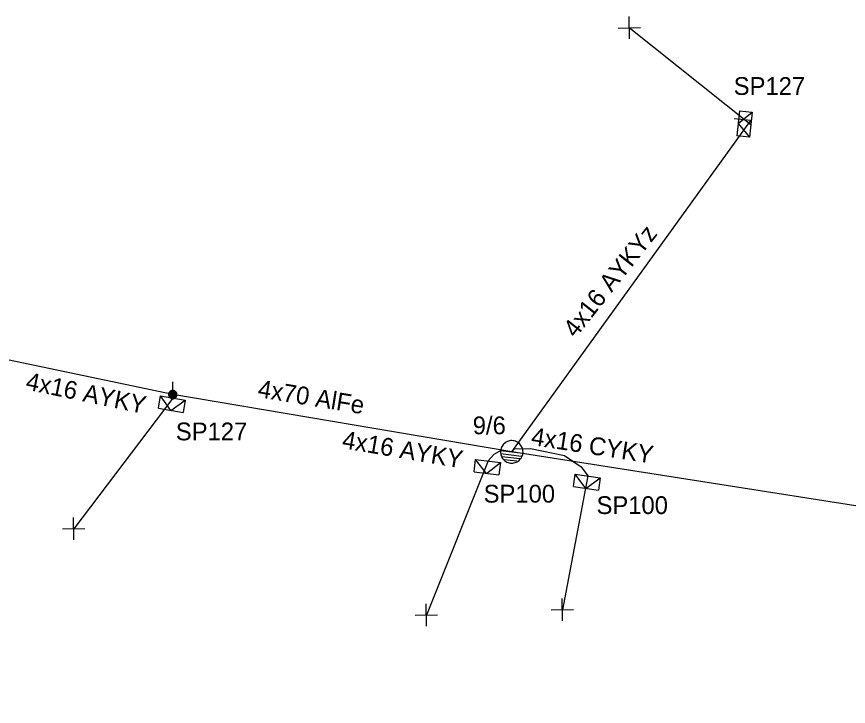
# Model space of a CAD drawing. Extents: x -762504 to -761250, y -1152974 to -1152253.
# Drawn here: x -761447.44 to -761400.94, y -1152551.93 to -1152513.38 of the extents above; entities that cross this region are included whole.
import ezdxf

# ---------------------------------------------------------------- set-up
doc = ezdxf.new("R2010")
doc.units = 0
for name, color, linetype in [('Vrstva 1', 7, 'Continuous'), ('Vrstva 12', 7, 'Continuous'), ('Vrstva 13', 7, 'Continuous'), ('Vrstva 2', 7, 'Continuous'), ('Vrstva 31', 7, 'Continuous'), ('Vrstva 33', 7, 'Continuous'), ('Vrstva 34', 7, 'Continuous'), ('Vrstva 52', 7, 'Continuous'), ('Vrstva 54', 7, 'Continuous'), ('Vrstva 55', 7, 'Continuous'), ('Vrstva 59', 7, 'Continuous')]:
    doc.layers.add(name, color=color, linetype=linetype)

msp = doc.modelspace()

# ---------------------------------------------------------------- linework, layer by layer
at = {"layer": 'Vrstva 1'}
msp.add_lwpolyline([(-761359.26, -1152551.93), (-761388.43, -1152542.63), (-761419.76, -1152537.7), (-761438.71, -1152534.5), (-761457.83, -1152530.5)], dxfattribs=at)
at = {"layer": 'Vrstva 13'}
for points in [[(-761406.392, -1152519.189), (-761407.324, -1152519.091)], [(-761438.71, -1152534.266), (-761438.71, -1152533.796)], [(-761438.475, -1152534.501), (-761438.476, -1152534.477), (-761438.48, -1152534.452), (-761438.486, -1152534.429), (-761438.495, -1152534.406), (-761438.506, -1152534.384), (-761438.519, -1152534.363), (-761438.535, -1152534.344), (-761438.552, -1152534.327), (-761438.571, -1152534.311), (-761438.592, -1152534.298), (-761438.614, -1152534.287), (-761438.637, -1152534.278), (-761438.661, -1152534.271), (-761438.685, -1152534.267), (-761438.71, -1152534.266), (-761438.734, -1152534.267), (-761438.758, -1152534.271), (-761438.782, -1152534.278), (-761438.805, -1152534.287), (-761438.827, -1152534.298), (-761438.848, -1152534.311), (-761438.867, -1152534.327), (-761438.884, -1152534.344), (-761438.9, -1152534.363), (-761438.913, -1152534.384), (-761438.924, -1152534.406), (-761438.933, -1152534.429), (-761438.939, -1152534.452), (-761438.943, -1152534.477), (-761438.945, -1152534.501), (-761438.943, -1152534.526), (-761438.939, -1152534.55), (-761438.933, -1152534.574), (-761438.924, -1152534.597), (-761438.913, -1152534.619), (-761438.9, -1152534.639), (-761438.884, -1152534.658), (-761438.867, -1152534.676), (-761438.848, -1152534.691), (-761438.827, -1152534.705), (-761438.805, -1152534.716), (-761438.782, -1152534.725), (-761438.758, -1152534.731), (-761438.734, -1152534.735), (-761438.71, -1152534.736), (-761438.685, -1152534.735), (-761438.661, -1152534.731), (-761438.637, -1152534.725), (-761438.614, -1152534.716), (-761438.592, -1152534.705), (-761438.571, -1152534.691), (-761438.552, -1152534.676), (-761438.535, -1152534.658), (-761438.519, -1152534.639), (-761438.506, -1152534.619), (-761438.495, -1152534.597), (-761438.486, -1152534.574), (-761438.48, -1152534.55), (-761438.476, -1152534.526), (-761438.475, -1152534.501)], [(-761438.475, -1152534.501), (-761438.476, -1152534.477), (-761438.48, -1152534.452), (-761438.486, -1152534.429), (-761438.495, -1152534.406), (-761438.506, -1152534.384), (-761438.519, -1152534.363), (-761438.535, -1152534.344), (-761438.552, -1152534.327), (-761438.571, -1152534.311), (-761438.592, -1152534.298), (-761438.614, -1152534.287), (-761438.637, -1152534.278), (-761438.661, -1152534.271), (-761438.685, -1152534.267), (-761438.71, -1152534.266), (-761438.734, -1152534.267), (-761438.758, -1152534.271), (-761438.782, -1152534.278), (-761438.805, -1152534.287), (-761438.827, -1152534.298), (-761438.848, -1152534.311), (-761438.867, -1152534.327), (-761438.884, -1152534.344), (-761438.9, -1152534.363), (-761438.913, -1152534.384), (-761438.924, -1152534.406), (-761438.933, -1152534.429), (-761438.939, -1152534.452), (-761438.943, -1152534.477), (-761438.945, -1152534.501), (-761438.943, -1152534.526), (-761438.939, -1152534.55), (-761438.933, -1152534.574), (-761438.924, -1152534.597), (-761438.913, -1152534.619), (-761438.9, -1152534.639), (-761438.884, -1152534.658), (-761438.867, -1152534.676), (-761438.848, -1152534.691), (-761438.827, -1152534.705), (-761438.805, -1152534.716), (-761438.782, -1152534.725), (-761438.758, -1152534.731), (-761438.734, -1152534.735), (-761438.71, -1152534.736), (-761438.685, -1152534.735), (-761438.661, -1152534.731), (-761438.637, -1152534.725), (-761438.614, -1152534.716), (-761438.592, -1152534.705), (-761438.571, -1152534.691), (-761438.552, -1152534.676), (-761438.535, -1152534.658), (-761438.519, -1152534.639), (-761438.506, -1152534.619), (-761438.495, -1152534.597), (-761438.486, -1152534.574), (-761438.48, -1152534.55), (-761438.476, -1152534.526), (-761438.475, -1152534.501)], [(-761438.504, -1152534.501), (-761438.505, -1152534.48), (-761438.509, -1152534.458), (-761438.514, -1152534.438), (-761438.522, -1152534.418), (-761438.532, -1152534.399), (-761438.543, -1152534.38), (-761438.557, -1152534.364), (-761438.572, -1152534.349), (-761438.589, -1152534.335), (-761438.607, -1152534.323), (-761438.626, -1152534.314), (-761438.646, -1152534.306), (-761438.667, -1152534.3), (-761438.688, -1152534.297), (-761438.71, -1152534.296), (-761438.731, -1152534.297), (-761438.752, -1152534.3), (-761438.773, -1152534.306), (-761438.793, -1152534.314), (-761438.812, -1152534.323), (-761438.83, -1152534.335), (-761438.847, -1152534.349), (-761438.862, -1152534.364), (-761438.876, -1152534.38), (-761438.887, -1152534.399), (-761438.897, -1152534.418), (-761438.905, -1152534.438), (-761438.91, -1152534.458), (-761438.914, -1152534.48), (-761438.915, -1152534.501), (-761438.914, -1152534.523), (-761438.91, -1152534.544), (-761438.905, -1152534.565), (-761438.897, -1152534.585), (-761438.887, -1152534.604), (-761438.876, -1152534.622), (-761438.862, -1152534.639), (-761438.847, -1152534.654), (-761438.83, -1152534.667), (-761438.812, -1152534.679), (-761438.793, -1152534.689), (-761438.773, -1152534.697), (-761438.752, -1152534.702), (-761438.731, -1152534.705), (-761438.71, -1152534.707), (-761438.688, -1152534.705), (-761438.667, -1152534.702), (-761438.646, -1152534.697), (-761438.626, -1152534.689), (-761438.607, -1152534.679), (-761438.589, -1152534.667), (-761438.572, -1152534.654), (-761438.557, -1152534.639), (-761438.543, -1152534.622), (-761438.532, -1152534.604), (-761438.522, -1152534.585), (-761438.514, -1152534.565), (-761438.509, -1152534.544), (-761438.505, -1152534.523), (-761438.504, -1152534.501)], [(-761438.534, -1152534.501), (-761438.535, -1152534.483), (-761438.538, -1152534.465), (-761438.542, -1152534.447), (-761438.549, -1152534.43), (-761438.557, -1152534.413), (-761438.567, -1152534.398), (-761438.579, -1152534.384), (-761438.592, -1152534.371), (-761438.606, -1152534.359), (-761438.622, -1152534.349), (-761438.638, -1152534.341), (-761438.655, -1152534.334), (-761438.673, -1152534.329), (-761438.691, -1152534.326), (-761438.71, -1152534.325), (-761438.728, -1152534.326), (-761438.746, -1152534.329), (-761438.764, -1152534.334), (-761438.781, -1152534.341), (-761438.797, -1152534.349), (-761438.813, -1152534.359), (-761438.827, -1152534.371), (-761438.84, -1152534.384), (-761438.852, -1152534.398), (-761438.862, -1152534.413), (-761438.87, -1152534.43), (-761438.877, -1152534.447), (-761438.881, -1152534.465), (-761438.884, -1152534.483), (-761438.885, -1152534.501), (-761438.884, -1152534.52), (-761438.881, -1152534.538), (-761438.877, -1152534.555), (-761438.87, -1152534.573), (-761438.862, -1152534.589), (-761438.852, -1152534.604), (-761438.84, -1152534.619), (-761438.827, -1152534.632), (-761438.813, -1152534.643), (-761438.797, -1152534.653), (-761438.781, -1152534.662), (-761438.764, -1152534.668), (-761438.746, -1152534.673), (-761438.728, -1152534.676), (-761438.71, -1152534.677), (-761438.691, -1152534.676), (-761438.673, -1152534.673), (-761438.655, -1152534.668), (-761438.638, -1152534.662), (-761438.622, -1152534.653), (-761438.606, -1152534.643), (-761438.592, -1152534.632), (-761438.579, -1152534.619), (-761438.567, -1152534.604), (-761438.557, -1152534.589), (-761438.549, -1152534.573), (-761438.542, -1152534.555), (-761438.538, -1152534.538), (-761438.535, -1152534.52), (-761438.534, -1152534.501)], [(-761438.563, -1152534.501), (-761438.564, -1152534.486), (-761438.567, -1152534.471), (-761438.571, -1152534.456), (-761438.576, -1152534.442), (-761438.583, -1152534.428), (-761438.591, -1152534.415), (-761438.601, -1152534.403), (-761438.612, -1152534.393), (-761438.624, -1152534.383), (-761438.637, -1152534.375), (-761438.65, -1152534.368), (-761438.664, -1152534.362), (-761438.679, -1152534.358), (-761438.694, -1152534.356), (-761438.71, -1152534.355), (-761438.725, -1152534.356), (-761438.74, -1152534.358), (-761438.755, -1152534.362), (-761438.769, -1152534.368), (-761438.783, -1152534.375), (-761438.795, -1152534.383), (-761438.807, -1152534.393), (-761438.818, -1152534.403), (-761438.828, -1152534.415), (-761438.836, -1152534.428), (-761438.843, -1152534.442), (-761438.849, -1152534.456), (-761438.853, -1152534.471), (-761438.855, -1152534.486), (-761438.856, -1152534.501), (-761438.855, -1152534.516), (-761438.853, -1152534.532), (-761438.849, -1152534.546), (-761438.843, -1152534.561), (-761438.836, -1152534.574), (-761438.828, -1152534.587), (-761438.818, -1152534.599), (-761438.807, -1152534.61), (-761438.795, -1152534.619), (-761438.783, -1152534.628), (-761438.769, -1152534.635), (-761438.755, -1152534.64), (-761438.74, -1152534.644), (-761438.725, -1152534.647), (-761438.71, -1152534.647), (-761438.694, -1152534.647), (-761438.679, -1152534.644), (-761438.664, -1152534.64), (-761438.65, -1152534.635), (-761438.637, -1152534.628), (-761438.624, -1152534.619), (-761438.612, -1152534.61), (-761438.601, -1152534.599), (-761438.591, -1152534.587), (-761438.583, -1152534.574), (-761438.576, -1152534.561), (-761438.571, -1152534.546), (-761438.567, -1152534.532), (-761438.564, -1152534.516), (-761438.563, -1152534.501)], [(-761438.593, -1152534.501), (-761438.594, -1152534.489), (-761438.596, -1152534.477), (-761438.599, -1152534.465), (-761438.603, -1152534.454), (-761438.609, -1152534.443), (-761438.615, -1152534.433), (-761438.623, -1152534.423), (-761438.632, -1152534.415), (-761438.641, -1152534.407), (-761438.651, -1152534.4), (-761438.662, -1152534.395), (-761438.674, -1152534.39), (-761438.685, -1152534.387), (-761438.697, -1152534.385), (-761438.71, -1152534.385), (-761438.722, -1152534.385), (-761438.734, -1152534.387), (-761438.746, -1152534.39), (-761438.757, -1152534.395), (-761438.768, -1152534.4), (-761438.778, -1152534.407), (-761438.788, -1152534.415), (-761438.796, -1152534.423), (-761438.804, -1152534.433), (-761438.811, -1152534.443), (-761438.816, -1152534.454), (-761438.82, -1152534.465), (-761438.824, -1152534.477), (-761438.826, -1152534.489), (-761438.826, -1152534.501), (-761438.826, -1152534.513), (-761438.824, -1152534.525), (-761438.82, -1152534.537), (-761438.816, -1152534.549), (-761438.811, -1152534.559), (-761438.804, -1152534.57), (-761438.796, -1152534.579), (-761438.788, -1152534.588), (-761438.778, -1152534.595), (-761438.768, -1152534.602), (-761438.757, -1152534.608), (-761438.746, -1152534.612), (-761438.734, -1152534.615), (-761438.722, -1152534.617), (-761438.71, -1152534.618), (-761438.697, -1152534.617), (-761438.685, -1152534.615), (-761438.674, -1152534.612), (-761438.662, -1152534.608), (-761438.651, -1152534.602), (-761438.641, -1152534.595), (-761438.632, -1152534.588), (-761438.623, -1152534.579), (-761438.615, -1152534.57), (-761438.609, -1152534.559), (-761438.603, -1152534.549), (-761438.599, -1152534.537), (-761438.596, -1152534.525), (-761438.594, -1152534.513), (-761438.593, -1152534.501)], [(-761438.623, -1152534.501), (-761438.623, -1152534.492), (-761438.625, -1152534.483), (-761438.627, -1152534.474), (-761438.63, -1152534.466), (-761438.634, -1152534.458), (-761438.639, -1152534.45), (-761438.645, -1152534.443), (-761438.651, -1152534.437), (-761438.658, -1152534.431), (-761438.666, -1152534.426), (-761438.674, -1152534.422), (-761438.683, -1152534.418), (-761438.691, -1152534.416), (-761438.7, -1152534.415), (-761438.71, -1152534.414), (-761438.719, -1152534.415), (-761438.728, -1152534.416), (-761438.736, -1152534.418), (-761438.745, -1152534.422), (-761438.753, -1152534.426), (-761438.761, -1152534.431), (-761438.768, -1152534.437), (-761438.774, -1152534.443), (-761438.78, -1152534.45), (-761438.785, -1152534.458), (-761438.789, -1152534.466), (-761438.792, -1152534.474), (-761438.795, -1152534.483), (-761438.796, -1152534.492), (-761438.797, -1152534.501), (-761438.796, -1152534.51), (-761438.795, -1152534.519), (-761438.792, -1152534.528), (-761438.789, -1152534.537), (-761438.785, -1152534.545), (-761438.78, -1152534.552), (-761438.774, -1152534.559), (-761438.768, -1152534.566), (-761438.761, -1152534.572), (-761438.753, -1152534.576), (-761438.745, -1152534.581), (-761438.736, -1152534.584), (-761438.728, -1152534.586), (-761438.719, -1152534.588), (-761438.71, -1152534.588), (-761438.7, -1152534.588), (-761438.691, -1152534.586), (-761438.683, -1152534.584), (-761438.674, -1152534.581), (-761438.666, -1152534.576), (-761438.658, -1152534.572), (-761438.651, -1152534.566), (-761438.645, -1152534.559), (-761438.639, -1152534.552), (-761438.634, -1152534.545), (-761438.63, -1152534.537), (-761438.627, -1152534.528), (-761438.625, -1152534.519), (-761438.623, -1152534.51), (-761438.623, -1152534.501)], [(-761438.652, -1152534.501), (-761438.653, -1152534.495), (-761438.653, -1152534.489), (-761438.655, -1152534.483), (-761438.657, -1152534.478), (-761438.66, -1152534.473), (-761438.663, -1152534.467), (-761438.667, -1152534.463), (-761438.671, -1152534.459), (-761438.676, -1152534.455), (-761438.681, -1152534.452), (-761438.686, -1152534.449), (-761438.692, -1152534.447), (-761438.698, -1152534.445), (-761438.704, -1152534.444), (-761438.71, -1152534.444), (-761438.716, -1152534.444), (-761438.721, -1152534.445), (-761438.727, -1152534.447), (-761438.733, -1152534.449), (-761438.738, -1152534.452), (-761438.743, -1152534.455), (-761438.748, -1152534.459), (-761438.752, -1152534.463), (-761438.756, -1152534.467), (-761438.759, -1152534.473), (-761438.762, -1152534.478), (-761438.764, -1152534.483), (-761438.766, -1152534.489), (-761438.767, -1152534.495), (-761438.767, -1152534.501), (-761438.767, -1152534.507), (-761438.766, -1152534.513), (-761438.764, -1152534.519), (-761438.762, -1152534.525), (-761438.759, -1152534.53), (-761438.756, -1152534.535), (-761438.752, -1152534.54), (-761438.748, -1152534.544), (-761438.743, -1152534.548), (-761438.738, -1152534.551), (-761438.733, -1152534.554), (-761438.727, -1152534.556), (-761438.721, -1152534.557), (-761438.716, -1152534.558), (-761438.71, -1152534.559), (-761438.704, -1152534.558), (-761438.698, -1152534.557), (-761438.692, -1152534.556), (-761438.686, -1152534.554), (-761438.681, -1152534.551), (-761438.676, -1152534.548), (-761438.671, -1152534.544), (-761438.667, -1152534.54), (-761438.663, -1152534.535), (-761438.66, -1152534.53), (-761438.657, -1152534.525), (-761438.655, -1152534.519), (-761438.653, -1152534.513), (-761438.653, -1152534.507), (-761438.652, -1152534.501)], [(-761438.682, -1152534.501), (-761438.682, -1152534.498), (-761438.682, -1152534.495), (-761438.683, -1152534.493), (-761438.684, -1152534.49), (-761438.686, -1152534.487), (-761438.687, -1152534.485), (-761438.689, -1152534.483), (-761438.691, -1152534.481), (-761438.693, -1152534.479), (-761438.696, -1152534.477), (-761438.698, -1152534.476), (-761438.701, -1152534.475), (-761438.704, -1152534.474), (-761438.707, -1152534.474), (-761438.71, -1152534.473), (-761438.712, -1152534.474), (-761438.715, -1152534.474), (-761438.718, -1152534.475), (-761438.721, -1152534.476), (-761438.723, -1152534.477), (-761438.726, -1152534.479), (-761438.728, -1152534.481), (-761438.73, -1152534.483), (-761438.732, -1152534.485), (-761438.734, -1152534.487), (-761438.735, -1152534.49), (-761438.736, -1152534.493), (-761438.737, -1152534.495), (-761438.737, -1152534.498), (-761438.737, -1152534.501), (-761438.737, -1152534.504), (-761438.737, -1152534.507), (-761438.736, -1152534.51), (-761438.735, -1152534.512), (-761438.734, -1152534.515), (-761438.732, -1152534.518), (-761438.73, -1152534.52), (-761438.728, -1152534.522), (-761438.726, -1152534.524), (-761438.723, -1152534.525), (-761438.721, -1152534.527), (-761438.718, -1152534.528), (-761438.715, -1152534.528), (-761438.712, -1152534.529), (-761438.71, -1152534.529), (-761438.707, -1152534.529), (-761438.704, -1152534.528), (-761438.701, -1152534.528), (-761438.698, -1152534.527), (-761438.696, -1152534.525), (-761438.693, -1152534.524), (-761438.691, -1152534.522), (-761438.689, -1152534.52), (-761438.687, -1152534.518), (-761438.686, -1152534.515), (-761438.684, -1152534.512), (-761438.683, -1152534.51), (-761438.682, -1152534.507), (-761438.682, -1152534.504), (-761438.682, -1152534.501)], [(-761419.135, -1152537.781), (-761419.13, -1152537.716), (-761419.132, -1152537.65), (-761419.141, -1152537.584), (-761419.157, -1152537.52), (-761419.18, -1152537.459), (-761419.209, -1152537.399), (-761419.244, -1152537.343), (-761419.284, -1152537.291), (-761419.33, -1152537.244), (-761419.381, -1152537.201), (-761419.435, -1152537.165), (-761419.494, -1152537.134), (-761419.555, -1152537.109), (-761419.618, -1152537.091), (-761419.683, -1152537.079), (-761419.749, -1152537.075), (-761419.815, -1152537.077), (-761419.88, -1152537.086), (-761419.944, -1152537.102), (-761420.006, -1152537.125), (-761420.065, -1152537.154), (-761420.121, -1152537.189), (-761420.173, -1152537.229), (-761420.221, -1152537.275), (-761420.263, -1152537.326), (-761420.3, -1152537.38), (-761420.331, -1152537.438), (-761420.355, -1152537.5), (-761420.374, -1152537.563), (-761420.385, -1152537.628), (-761420.39, -1152537.694), (-761420.387, -1152537.76), (-761420.378, -1152537.825), (-761420.362, -1152537.889), (-761420.339, -1152537.951), (-761420.311, -1152538.01), (-761420.276, -1152538.066), (-761420.235, -1152538.118), (-761420.189, -1152538.165), (-761420.139, -1152538.208), (-761420.084, -1152538.245), (-761420.026, -1152538.276), (-761419.965, -1152538.3), (-761419.901, -1152538.319), (-761419.837, -1152538.33), (-761419.771, -1152538.335), (-761419.705, -1152538.332), (-761419.64, -1152538.323), (-761419.576, -1152538.307), (-761419.514, -1152538.285), (-761419.454, -1152538.256), (-761419.398, -1152538.221), (-761419.347, -1152538.18), (-761419.299, -1152538.134), (-761419.257, -1152538.084), (-761419.22, -1152538.029), (-761419.189, -1152537.971), (-761419.164, -1152537.91), (-761419.146, -1152537.846), (-761419.135, -1152537.781)], [(-761420.386, -1152537.624), (-761419.136, -1152537.777)], [(-761420.379, -1152537.803), (-761419.216, -1152537.946)], [(-761420.309, -1152537.96), (-761419.302, -1152538.084)], [(-761420.19, -1152538.124), (-761419.467, -1152538.213)]]:
    msp.add_lwpolyline(points, dxfattribs=at)
at = {"layer": 'Vrstva 31'}
for points in [[(-761407.023, -1152518.648), (-761407.169, -1152520.04)], [(-761407.023, -1152518.648), (-761406.327, -1152518.721), (-761406.473, -1152520.113), (-761407.169, -1152520.04)], [(-761407.096, -1152519.344), (-761406.327, -1152518.721)], [(-761407.096, -1152519.344), (-761406.473, -1152520.113)], [(-761439.514, -1152535.268), (-761439.392, -1152534.578), (-761438.014, -1152534.821), (-761438.135, -1152535.511)], [(-761438.825, -1152535.389), (-761439.392, -1152534.578)], [(-761438.825, -1152535.389), (-761438.014, -1152534.821)], [(-761439.514, -1152535.268), (-761438.135, -1152535.511)], [(-761421.863, -1152538.819), (-761421.778, -1152538.125), (-761420.388, -1152538.295), (-761420.473, -1152538.99)], [(-761421.168, -1152538.905), (-761421.778, -1152538.125)], [(-761421.168, -1152538.905), (-761420.388, -1152538.295)], [(-761421.863, -1152538.819), (-761420.473, -1152538.99)], [(-761416.304, -1152539.646), (-761416.206, -1152538.953), (-761414.82, -1152539.147), (-761414.917, -1152539.841)], [(-761415.61, -1152539.743), (-761416.206, -1152538.953)], [(-761415.61, -1152539.743), (-761414.82, -1152539.147)], [(-761416.304, -1152539.646), (-761414.917, -1152539.841)]]:
    msp.add_lwpolyline(points, dxfattribs=at)
at = {"layer": 'Vrstva 34'}
for points in [[(-761413.179, -1152514.625), (-761413.201, -1152513.375)], [(-761413.815, -1152514.011), (-761412.565, -1152513.989)], [(-761444.239, -1152542.625), (-761444.261, -1152541.375)], [(-761444.875, -1152542.011), (-761443.625, -1152541.989)], [(-761416.919, -1152547.155), (-761416.941, -1152545.905)], [(-761424.519, -1152547.455), (-761424.541, -1152546.205)], [(-761417.555, -1152546.541), (-761416.305, -1152546.519)], [(-761425.155, -1152546.841), (-761423.905, -1152546.819)]]:
    msp.add_lwpolyline(points, dxfattribs=at)
at = {"layer": 'Vrstva 52'}
for points in [[(-761438.71, -1152534.5), (-761438.7, -1152534.7)], [(-761419.76, -1152537.7), (-761420.37, -1152537.63), (-761420.77, -1152537.86), (-761421.08, -1152538.21)], [(-761419.76, -1152537.7), (-761419.61, -1152537.53), (-761418.72, -1152537.52), (-761416.81, -1152537.9), (-761415.87, -1152538.54), (-761415.51, -1152539.05)]]:
    msp.add_lwpolyline(points, dxfattribs=at)
at = {"layer": 'Vrstva 54'}
msp.add_lwpolyline([(-761419.76, -1152537.7), (-761406.39, -1152519.19), (-761406.4, -1152519.42)], dxfattribs=at)
at = {"layer": 'Vrstva 59'}
for points in [[(-761406.4, -1152519.42), (-761413.19, -1152514)], [(-761438.7, -1152534.7), (-761444.25, -1152542)], [(-761421.08, -1152538.21), (-761424.53, -1152546.83)], [(-761415.51, -1152539.05), (-761416.93, -1152546.53)]]:
    msp.add_lwpolyline(points, dxfattribs=at)

# ---------------------------------------------------------------- texts
at = {"layer": 'Vrstva 12'}
msp.add_text('9/6', height=0.9943, dxfattribs=at).set_placement((-761421.94, -1152536.72))
at = {"layer": 'Vrstva 2'}
msp.add_text('4x70 AlFe', height=0.9943, rotation=350.7701, dxfattribs=at).set_placement((-761434, -1152534.64))
at = {"layer": 'Vrstva 33'}
for s, p in [('SP127', (-761407.35, -1152517.75)), ('SP127', (-761438.54, -1152537.06)), ('SP100', (-761421.33, -1152540.54)), ('SP100', (-761415.02, -1152541.18))]:
    msp.add_text(s, height=0.9943, dxfattribs=at).set_placement(p)
at = {"layer": 'Vrstva 54'}
for s, rotation, p in [('4x16 AYKY', 348.3073, (-761446.98, -1152534.21)), ('4x16 AYKY', 350.3625, (-761429.29, -1152537.49)), ('4x16 CYKY', 351.1796, (-761418.72, -1152537.31))]:
    msp.add_text(s, height=0.9943, rotation=rotation, dxfattribs=at).set_placement(p)
at = {"layer": 'Vrstva 55'}
msp.add_text('4x16 AYKYz', height=0.9943, rotation=51.7258, dxfattribs=at).set_placement((-761416.19, -1152531.38))

doc.saveas('drawing.dxf')
